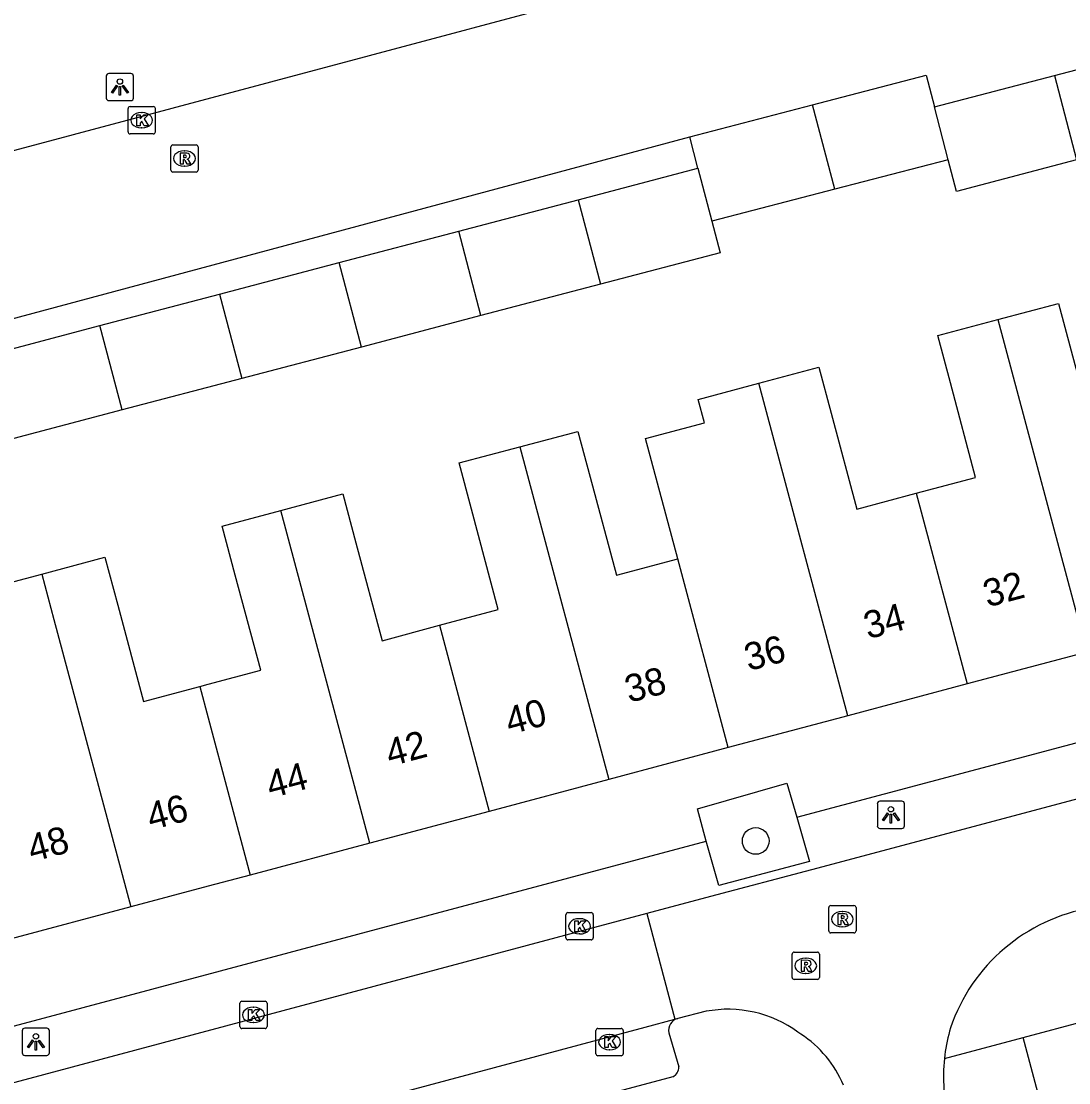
# Model space of a CAD drawing. Extents: x 162542 to 163144, y 380786 to 381511.
# Drawn here: x 162993.14 to 163031.56, y 381118.47 to 381157.4 of the extents above; entities that cross this region are included whole.
import ezdxf

# ---------------------------------------------------------------- set-up
doc = ezdxf.new("R2010")
doc.units = 0
for name, color, linetype in [('IMGEO_Boom', 7, 'Continuous'), ('IMGEO_Kolk', 7, 'Continuous'), ('IMGEO_Lichtpunt', 7, 'Continuous'), ('IMGEO_Pand', 7, 'Continuous'), ('IMGEO_Pand_nummerreeks', 7, 'Continuous'), ('IMGEO_Parkeervlak_open', 7, 'Continuous'), ('IMGEO_Rijbaan_lokaal_open', 7, 'Continuous'), ('IMGEO_Rioolput', 7, 'Continuous'), ('IMGEO_Voetpad_open', 7, 'Continuous')]:
    doc.layers.add(name, color=color, linetype=linetype)

msp = doc.modelspace()

# ---------------------------------------------------------------- linework, layer by layer
at = {"layer": 'IMGEO_Boom'}
msp.add_circle((163020.078, 381127.337), 0.489, dxfattribs=at)
at = {"layer": 'IMGEO_Kolk'}
for p, q in [((162997.059, 381153.341), (162997.059, 381154.193)), ((162997.134, 381154.267), (162997.986, 381154.267)), ((162998.06, 381154.193), (162998.06, 381153.341)), ((162997.547, 381154.047), (162997.572, 381154.047)), ((162997.57, 381153.487), (162997.545, 381153.487)), ((162997.986, 381153.267), (162997.134, 381153.267)), ((163013.118, 381123.782), (163013.118, 381124.634)), ((163013.193, 381124.708), (163014.045, 381124.708)), ((163014.119, 381124.634), (163014.119, 381123.782)), ((163013.606, 381124.488), (163013.631, 381124.488)), ((163013.629, 381123.928), (163013.604, 381123.928)), ((163014.045, 381123.708), (163013.193, 381123.708)), ((163001.159, 381120.532), (163001.159, 381121.384)), ((163001.234, 381121.458), (163002.086, 381121.458)), ((163002.16, 381121.384), (163002.16, 381120.532)), ((163001.647, 381121.238), (163001.672, 381121.238)), ((163001.67, 381120.678), (163001.645, 381120.678)), ((163002.086, 381120.458), (163001.234, 381120.458)), ((163014.218, 381119.536), (163014.218, 381120.388)), ((163014.293, 381120.462), (163015.145, 381120.462)), ((163014.706, 381120.242), (163014.731, 381120.242)), ((163015.219, 381120.388), (163015.219, 381119.536)), ((163015.145, 381119.462), (163014.293, 381119.462)), ((163014.729, 381119.682), (163014.704, 381119.682))]:
    msp.add_line(p, q, dxfattribs=at)
for points in [[(162997.059, 381153.341), (162997.059, 381154.193)], [(162997.134, 381154.267), (162997.986, 381154.267)], [(162998.06, 381154.193), (162998.06, 381153.341)], [(162997.38, 381153.967), (162997.503, 381153.967), (162997.503, 381153.816), (162997.633, 381153.967), (162997.797, 381153.967), (162997.651, 381153.816), (162997.804, 381153.567), (162997.652, 381153.567), (162997.567, 381153.731), (162997.503, 381153.664), (162997.503, 381153.567), (162997.38, 381153.567), (162997.38, 381153.967)], [(162997.986, 381153.267), (162997.134, 381153.267)], [(163013.118, 381123.782), (163013.118, 381124.634)], [(163013.193, 381124.708), (163014.045, 381124.708)], [(163014.119, 381124.634), (163014.119, 381123.782)], [(163013.439, 381124.408), (163013.562, 381124.408), (163013.562, 381124.257), (163013.692, 381124.408), (163013.856, 381124.408), (163013.71, 381124.257), (163013.863, 381124.008), (163013.711, 381124.008), (163013.626, 381124.172), (163013.562, 381124.105), (163013.562, 381124.008), (163013.439, 381124.008), (163013.439, 381124.408)], [(163014.045, 381123.708), (163013.193, 381123.708)], [(163001.159, 381120.532), (163001.159, 381121.384)], [(163001.234, 381121.458), (163002.086, 381121.458)], [(163002.16, 381121.384), (163002.16, 381120.532)], [(163001.48, 381121.158), (163001.603, 381121.158), (163001.603, 381121.007), (163001.733, 381121.158), (163001.897, 381121.158), (163001.751, 381121.007), (163001.904, 381120.758), (163001.752, 381120.758), (163001.667, 381120.922), (163001.603, 381120.855), (163001.603, 381120.758), (163001.48, 381120.758), (163001.48, 381121.158)], [(163002.086, 381120.458), (163001.234, 381120.458)], [(163014.218, 381119.536), (163014.218, 381120.388)], [(163014.293, 381120.462), (163015.145, 381120.462)], [(163015.219, 381120.388), (163015.219, 381119.536)], [(163014.539, 381120.162), (163014.662, 381120.162), (163014.662, 381120.011), (163014.792, 381120.162), (163014.956, 381120.162), (163014.81, 381120.011), (163014.963, 381119.762), (163014.811, 381119.762), (163014.726, 381119.926), (163014.662, 381119.859), (163014.662, 381119.762), (163014.539, 381119.762), (163014.539, 381120.162)], [(163015.145, 381119.462), (163014.293, 381119.462)]]:
    msp.add_lwpolyline(points, dxfattribs=at)
for centre, start, end in [((162997.136, 381154.191), 91.552, 178.448), ((162997.136, 381154.191), 91.552, 178.448), ((162997.984, 381154.191), 1.552, 88.448), ((162997.984, 381154.191), 1.552, 88.448), ((162997.136, 381153.343), 181.552, 268.448), ((162997.136, 381153.343), 181.552, 268.448), ((162997.984, 381153.343), 271.552, 358.448), ((162997.984, 381153.343), 271.552, 358.448), ((163013.195, 381124.632), 91.552, 178.448), ((163013.195, 381124.632), 91.552, 178.448), ((163014.043, 381124.632), 1.552, 88.448), ((163014.043, 381124.632), 1.552, 88.448), ((163013.195, 381123.784), 181.552, 268.448), ((163013.195, 381123.784), 181.552, 268.448), ((163014.043, 381123.784), 271.552, 358.448), ((163014.043, 381123.784), 271.552, 358.448), ((163001.236, 381121.382), 91.552, 178.448), ((163001.236, 381121.382), 91.552, 178.448), ((163002.084, 381121.382), 1.552, 88.448), ((163002.084, 381121.382), 1.552, 88.448), ((163001.236, 381120.534), 181.552, 268.448), ((163001.236, 381120.534), 181.552, 268.448), ((163002.084, 381120.534), 271.552, 358.448), ((163002.084, 381120.534), 271.552, 358.448), ((163014.295, 381120.386), 91.552, 178.448), ((163014.295, 381120.386), 91.552, 178.448), ((163015.143, 381120.386), 1.552, 88.448), ((163015.143, 381120.386), 1.552, 88.448), ((163014.295, 381119.538), 181.552, 268.448), ((163014.295, 381119.538), 181.552, 268.448), ((163015.143, 381119.538), 271.552, 358.448), ((163015.143, 381119.538), 271.552, 358.448)]:
    msp.add_arc(centre, 0.0765, start, end, dxfattribs=at)
for centre, major_axis, ratio, start_param, end_param in [((162997.546, 381153.767), (-0.387, 0.002), 0.722429, 4.712389, 7.853982), ((162997.571, 381153.767), (-0.39, 0.002), 0.717154, 1.570796, 4.712389), ((163013.605, 381124.208), (-0.387, 0.002), 0.722429, 4.712389, 7.853982), ((163013.63, 381124.208), (-0.39, 0.002), 0.717154, 1.570796, 4.712389), ((163001.646, 381120.958), (-0.387, 0.002), 0.722429, 4.712389, 7.853982), ((163001.671, 381120.958), (-0.39, 0.002), 0.717154, 1.570796, 4.712389), ((163014.705, 381119.962), (-0.387, 0.002), 0.722429, 4.712389, 7.853982), ((163014.73, 381119.962), (-0.39, 0.002), 0.717154, 1.570796, 4.712389)]:
    msp.add_ellipse(centre, major_axis=major_axis, ratio=ratio, start_param=start_param, end_param=end_param, dxfattribs=at)
at = {"layer": 'IMGEO_Lichtpunt'}
for p, q in [((162996.262, 381155.388), (162996.262, 381154.581)), ((162996.262, 381155.388), (162996.262, 381154.581)), ((162997.164, 381155.483), (162996.356, 381155.483)), ((162997.164, 381155.483), (162996.356, 381155.483)), ((162997.258, 381154.581), (162997.258, 381155.388)), ((162997.258, 381154.581), (162997.258, 381155.388)), ((162996.356, 381154.487), (162997.164, 381154.487)), ((162996.356, 381154.487), (162997.164, 381154.487)), ((163025.441, 381128.796), (163024.633, 381128.796)), ((163025.441, 381128.796), (163024.633, 381128.796)), ((163024.539, 381128.701), (163024.539, 381127.894)), ((163024.539, 381128.701), (163024.539, 381127.894)), ((163025.535, 381127.894), (163025.535, 381128.701)), ((163025.535, 381127.894), (163025.535, 381128.701)), ((163024.633, 381127.8), (163025.441, 381127.8)), ((163024.633, 381127.8), (163025.441, 381127.8)), ((162993.179, 381120.375), (162993.179, 381119.568)), ((162993.179, 381120.375), (162993.179, 381119.568)), ((162994.081, 381120.47), (162993.273, 381120.47)), ((162994.081, 381120.47), (162993.273, 381120.47)), ((162994.175, 381119.568), (162994.175, 381120.375)), ((162994.175, 381119.568), (162994.175, 381120.375)), ((162993.273, 381119.474), (162994.081, 381119.474)), ((162993.273, 381119.474), (162994.081, 381119.474))]:
    msp.add_line(p, q, dxfattribs=at)
for points in [[(162996.636, 381155.052), (162996.675, 381155.024), (162996.487, 381154.762), (162996.449, 381154.789), (162996.636, 381155.052)], [(162996.738, 381155.004), (162996.785, 381155.004), (162996.785, 381154.682), (162996.738, 381154.682), (162996.738, 381155.004)], [(162996.848, 381155.024), (162996.886, 381155.051), (162997.073, 381154.789), (162997.034, 381154.761), (162996.848, 381155.024)], [(163024.913, 381128.365), (163024.952, 381128.337), (163024.764, 381128.075), (163024.726, 381128.102), (163024.913, 381128.365)], [(163025.015, 381128.317), (163025.062, 381128.317), (163025.062, 381127.995), (163025.015, 381127.995), (163025.015, 381128.317)], [(163025.125, 381128.337), (163025.163, 381128.364), (163025.35, 381128.102), (163025.311, 381128.074), (163025.125, 381128.337)], [(162993.553, 381120.039), (162993.592, 381120.011), (162993.404, 381119.749), (162993.366, 381119.776), (162993.553, 381120.039)], [(162993.655, 381119.991), (162993.702, 381119.991), (162993.702, 381119.669), (162993.655, 381119.669), (162993.655, 381119.991)], [(162993.765, 381120.011), (162993.803, 381120.038), (162993.99, 381119.776), (162993.951, 381119.748), (162993.765, 381120.011)]]:
    msp.add_lwpolyline(points, dxfattribs=at)
for centre in [(162996.761, 381155.186), (163025.038, 381128.499), (162993.678, 381120.173)]:
    msp.add_circle(centre, 0.0994, dxfattribs=at)
for centre, start, end in [((162996.356, 381155.388), 90, 180), ((162996.356, 381155.388), 90, 180), ((162997.164, 381155.388), 0, 90), ((162997.164, 381155.388), 0, 90), ((162996.356, 381154.581), 180, 270), ((162996.356, 381154.581), 180, 270), ((162997.164, 381154.581), 270, 0), ((162997.164, 381154.581), 270, 360), ((163024.633, 381128.701), 90, 180), ((163024.633, 381128.701), 90, 180), ((163025.441, 381128.701), 0, 90), ((163025.441, 381128.701), 0, 90), ((163024.633, 381127.894), 180, 270), ((163024.633, 381127.894), 180, 270), ((163025.441, 381127.894), 270, 0), ((163025.441, 381127.894), 270, 360), ((162993.273, 381120.375), 90, 180), ((162993.273, 381120.375), 90, 180), ((162994.081, 381120.375), 0, 90), ((162994.081, 381120.375), 0, 90), ((162993.273, 381119.568), 180, 270), ((162993.273, 381119.568), 180, 270), ((162994.081, 381119.568), 270, 0), ((162994.081, 381119.568), 270, 360)]:
    msp.add_arc(centre, 0.0946, start, end, dxfattribs=at)
at = {"layer": 'IMGEO_Pand'}
for points in [[(163031.035, 381155.407), (163035.437, 381156.559)], [(163022.155, 381154.33), (163026.331, 381155.417), (163026.633, 381154.256)], [(163026.633, 381154.256), (163031.035, 381155.407)], [(163031.035, 381155.407), (163031.845, 381152.311)], [(163017.659, 381153.159), (163022.155, 381154.33)], [(163022.982, 381151.238), (163022.155, 381154.33)], [(163027.142, 381152.321), (163026.633, 381154.256)], [(163017.959, 381152.006), (163017.659, 381153.159)], [(163027.142, 381152.321), (163022.982, 381151.238)], [(163031.845, 381152.311), (163027.444, 381151.16), (163027.142, 381152.321)], [(163013.573, 381150.852), (163017.959, 381152.006)], [(163017.959, 381152.006), (163018.47, 381150.064)], [(163022.982, 381151.238), (163018.47, 381150.064)], [(163009.188, 381149.699), (163013.573, 381150.852)], [(163013.573, 381150.852), (163014.387, 381147.758)], [(163018.47, 381150.064), (163018.77, 381148.91), (163014.387, 381147.758)], [(163004.802, 381148.545), (163009.188, 381149.699)], [(163010.002, 381146.604), (163009.188, 381149.699)], [(163000.416, 381147.392), (163004.802, 381148.545)], [(163005.616, 381145.45), (163004.802, 381148.545)], [(163014.387, 381147.758), (163010.002, 381146.604)], [(162996.03, 381146.238), (163000.416, 381147.392)], [(163000.416, 381147.392), (163001.23, 381144.297)], [(163028.956, 381146.456), (163031.181, 381147.048), (163031.644, 381145.316), (163032.572, 381141.847), (163034.729, 381142.423), (163035.008, 381141.379)], [(163010.002, 381146.604), (163005.616, 381145.45)], [(163025.965, 381140.087), (163028.145, 381140.67), (163027.219, 381144.132), (163026.754, 381145.87), (163028.956, 381146.456)], [(163028.956, 381146.456), (163032.218, 381134.261)], [(162991.644, 381145.084), (162996.03, 381146.238)], [(162996.844, 381143.143), (162996.03, 381146.238)], [(163005.616, 381145.45), (163001.23, 381144.297)], [(163020.191, 381144.124), (163022.392, 381144.709), (163022.842, 381143.027), (163023.784, 381139.504), (163025.965, 381140.087)], [(163001.23, 381144.297), (162996.844, 381143.143)], [(163017.219, 381137.683), (163016.039, 381142.093), (163018.197, 381142.67), (163017.966, 381143.532), (163020.191, 381144.124)], [(163023.454, 381131.926), (163020.191, 381144.124)], [(162996.844, 381143.143), (162992.458, 381141.99)], [(163011.425, 381141.791), (163013.557, 381142.358), (163014.008, 381140.673), (163014.969, 381137.081), (163017.219, 381137.683)], [(163008.481, 381135.245), (163010.639, 381135.822), (163009.653, 381139.509), (163009.201, 381141.199), (163011.425, 381141.791)], [(163011.425, 381141.791), (163014.689, 381129.591)], [(163025.965, 381140.087), (163027.836, 381133.094)], [(163002.66, 381139.458), (163004.935, 381140.063), (163005.416, 381138.265), (163006.375, 381134.681), (163008.481, 381135.245)], [(162999.692, 381133.001), (163000, 381133.083), (163001.924, 381133.597), (163000.992, 381137.082), (163000.51, 381138.886), (163002.66, 381139.458)], [(163005.924, 381127.255), (163002.66, 381139.458)], [(162993.895, 381137.125), (162996.214, 381137.742), (162996.683, 381135.989), (162997.629, 381132.449), (162999.692, 381133.001)], [(163019.072, 381130.759), (163017.219, 381137.683)], [(162991.927, 381135.594), (162991.675, 381136.534), (162993.895, 381137.125)], [(162993.895, 381137.125), (162994.342, 381135.454), (162997.16, 381124.92)], [(163008.481, 381135.245), (163010.306, 381128.423)], [(163032.218, 381134.261), (163027.836, 381133.094)], [(163027.836, 381133.094), (163023.454, 381131.926)], [(162999.692, 381133.001), (163000, 381131.85), (163001.542, 381126.088)], [(163023.454, 381131.926), (163019.072, 381130.759)], [(163019.072, 381130.759), (163014.689, 381129.591)], [(163014.689, 381129.591), (163010.306, 381128.423)], [(163010.306, 381128.423), (163005.924, 381127.255)], [(163005.924, 381127.255), (163001.542, 381126.088)], [(163001.542, 381126.088), (163000, 381125.677), (162997.16, 381124.92)], [(162997.16, 381124.92), (162992.778, 381123.753)], [(163029.891, 381120.133), (163034.458, 381121.35)], [(163033.149, 381107.868), (163032.705, 381109.54), (163029.891, 381120.133)]]:
    msp.add_lwpolyline(points, dxfattribs=at)
at = {"layer": 'IMGEO_Parkeervlak_open'}
msp.add_lwpolyline([(163021.581, 381128.205), (163022.045, 381126.58), (163018.732, 381125.705), (163018.261, 381127.332)], dxfattribs=at)
at = {"layer": 'IMGEO_Rijbaan_lokaal_open'}
for points in [[(162947.453, 381140.539), (163071.786, 381173.732)], [(162946.538, 381134.062), (163017.659, 381153.159)], [(163032.672, 381129.087), (163022.13, 381126.273), (163018.423, 381125.304), (163016.087, 381124.68)], [(163016.087, 381124.68), (162980.601, 381115.195), (162980.082, 381115.076), (162975.55, 381113.864)], [(163016.087, 381124.68), (163017.107, 381120.8)], [(163018.257, 381121.091), (163017.219, 381120.83)], [(162980.068, 381110.891), (163016.022, 381120.51), (163017.107, 381120.8)], [(163017.107, 381120.8), (163017.219, 381120.83)], [(163021.739, 381120.256), (163021.628, 381120.331)], [(163027.221, 381120.484), (163027.191, 381120.367)]]:
    msp.add_lwpolyline(points, dxfattribs=at)
for centre, radius, start, end in [((163033.504, 381118.338), 6.639, 99.7095, 161.1412), ((163019.062, 381116.803), 4.362, 53.9622, 100.6277), ((163019.41, 381116.732), 4.224, 22.9321, 56.5349), ((163033.071, 381118.723), 6.105, 164.3777, 173.9909), ((163033.071, 381118.715), 6.106, 173.9148, 195.0124)]:
    msp.add_arc(centre, radius, start, end, dxfattribs=at)
at = {"layer": 'IMGEO_Rioolput'}
for p, q in [((162998.628, 381151.938), (162998.628, 381152.79)), ((162998.703, 381152.864), (162999.555, 381152.864)), ((162999.116, 381152.644), (162999.141, 381152.644)), ((162999.629, 381152.79), (162999.629, 381151.938)), ((162999.555, 381151.864), (162998.703, 381151.864)), ((162999.139, 381152.084), (162999.114, 381152.084)), ((163022.756, 381124.042), (163022.756, 381124.894)), ((163022.831, 381124.968), (163023.683, 381124.968)), ((163023.757, 381124.894), (163023.757, 381124.042)), ((163023.244, 381124.748), (163023.269, 381124.748)), ((163023.267, 381124.188), (163023.242, 381124.188)), ((163023.683, 381123.968), (163022.831, 381123.968)), ((163021.412, 381122.334), (163021.412, 381123.186)), ((163021.487, 381123.26), (163022.339, 381123.26)), ((163021.9, 381123.04), (163021.925, 381123.04)), ((163022.413, 381123.186), (163022.413, 381122.334)), ((163022.339, 381122.26), (163021.487, 381122.26)), ((163021.923, 381122.48), (163021.898, 381122.48))]:
    msp.add_line(p, q, dxfattribs=at)
for points in [[(162998.628, 381151.938), (162998.628, 381152.79)], [(162998.703, 381152.864), (162999.555, 381152.864)], [(162999.217, 381152.562), (162998.965, 381152.564), (162998.965, 381152.164)], [(162999.629, 381152.79), (162999.629, 381151.938)], [(162998.965, 381152.164), (162999.089, 381152.164), (162999.089, 381152.326), (162999.1, 381152.326)], [(162999.143, 381152.483), (162999.089, 381152.483), (162999.089, 381152.402)], [(162999.089, 381152.402), (162999.141, 381152.402)], [(162999.147, 381152.297), (162999.218, 381152.164), (162999.358, 381152.164), (162999.293, 381152.29)], [(162999.555, 381151.864), (162998.703, 381151.864)], [(163022.756, 381124.042), (163022.756, 381124.894)], [(163022.831, 381124.968), (163023.683, 381124.968)], [(163023.757, 381124.894), (163023.757, 381124.042)], [(163023.345, 381124.666), (163023.093, 381124.668), (163023.093, 381124.268)], [(163023.271, 381124.587), (163023.217, 381124.587), (163023.217, 381124.506)], [(163023.217, 381124.506), (163023.269, 381124.506)], [(163023.093, 381124.268), (163023.217, 381124.268), (163023.217, 381124.43), (163023.228, 381124.43)], [(163023.275, 381124.401), (163023.346, 381124.268), (163023.486, 381124.268), (163023.421, 381124.394)], [(163023.683, 381123.968), (163022.831, 381123.968)], [(163021.412, 381122.334), (163021.412, 381123.186)], [(163021.487, 381123.26), (163022.339, 381123.26)], [(163022.001, 381122.958), (163021.749, 381122.96), (163021.749, 381122.56)], [(163022.413, 381123.186), (163022.413, 381122.334)], [(163021.749, 381122.56), (163021.873, 381122.56), (163021.873, 381122.722), (163021.884, 381122.722)], [(163021.927, 381122.879), (163021.873, 381122.879), (163021.873, 381122.798)], [(163021.873, 381122.798), (163021.925, 381122.798)], [(163021.931, 381122.693), (163022.002, 381122.56), (163022.142, 381122.56), (163022.077, 381122.686)], [(163022.339, 381122.26), (163021.487, 381122.26)]]:
    msp.add_lwpolyline(points, dxfattribs=at)
for centre, radius, start, end in [((162998.705, 381152.788), 0.0765, 91.552, 178.448), ((162998.705, 381152.788), 0.0765, 91.552, 178.448), ((162999.216, 381152.452), 0.109, 350.3612, 89.416), ((162999.553, 381152.788), 0.0765, 1.552, 88.448), ((162999.553, 381152.788), 0.0765, 1.552, 88.448), ((162999.099, 381152.273), 0.0533, 26.0293, 88.6989), ((162999.125, 381152.591), 0.19, 274.7715, 282.9687), ((162999.149, 381152.387), 0.0964, 77.0061, 93.1865), ((162999.163, 381152.444), 0.0378, 276.6634, 79.6772), ((162999.214, 381152.452), 0.112, 277.5842, 350.9817), ((162999.198, 381152.237), 0.108, 29.5134, 73.7905), ((162998.705, 381151.94), 0.0765, 181.552, 268.448), ((162998.705, 381151.94), 0.0765, 181.552, 268.448), ((162999.553, 381151.94), 0.0765, 271.552, 358.448), ((162999.553, 381151.94), 0.0765, 271.552, 358.448), ((163022.833, 381124.892), 0.0765, 91.552, 178.448), ((163022.833, 381124.892), 0.0765, 91.552, 178.448), ((163023.681, 381124.892), 0.0765, 1.552, 88.448), ((163023.681, 381124.892), 0.0765, 1.552, 88.448), ((163023.253, 381124.695), 0.19, 274.7715, 282.9687), ((163023.277, 381124.491), 0.0964, 77.0061, 93.1865), ((163023.291, 381124.548), 0.0378, 276.6634, 79.6772), ((163023.344, 381124.556), 0.109, 350.3612, 89.416), ((163023.342, 381124.556), 0.112, 277.5842, 350.9817), ((163023.227, 381124.377), 0.0533, 26.0293, 88.6989), ((163023.326, 381124.341), 0.108, 29.5134, 73.7905), ((163022.833, 381124.044), 0.0765, 181.552, 268.448), ((163022.833, 381124.044), 0.0765, 181.552, 268.448), ((163023.681, 381124.044), 0.0765, 271.552, 358.448), ((163023.681, 381124.044), 0.0765, 271.552, 358.448), ((163021.489, 381123.184), 0.0765, 91.552, 178.448), ((163021.489, 381123.184), 0.0765, 91.552, 178.448), ((163022, 381122.848), 0.109, 350.3612, 89.416), ((163022.337, 381123.184), 0.0765, 1.552, 88.448), ((163022.337, 381123.184), 0.0765, 1.552, 88.448), ((163021.883, 381122.669), 0.0533, 26.0293, 88.6989), ((163021.909, 381122.987), 0.19, 274.7715, 282.9687), ((163021.933, 381122.783), 0.0964, 77.0061, 93.1865), ((163021.947, 381122.84), 0.0378, 276.6634, 79.6772), ((163021.998, 381122.848), 0.112, 277.5842, 350.9817), ((163021.982, 381122.633), 0.108, 29.5134, 73.7905), ((163021.489, 381122.336), 0.0765, 181.552, 268.448), ((163021.489, 381122.336), 0.0765, 181.552, 268.448), ((163022.337, 381122.336), 0.0765, 271.552, 358.448), ((163022.337, 381122.336), 0.0765, 271.552, 358.448)]:
    msp.add_arc(centre, radius, start, end, dxfattribs=at)
for centre, major_axis, ratio, start_param, end_param in [((162999.115, 381152.364), (-0.387, 0.002), 0.722429, 4.712389, 7.853982), ((162999.14, 381152.364), (-0.39, 0.002), 0.717154, 1.570796, 4.712389), ((163023.243, 381124.468), (-0.387, 0.002), 0.722429, 4.712389, 7.853982), ((163023.268, 381124.468), (-0.39, 0.002), 0.717154, 1.570796, 4.712389), ((163021.899, 381122.76), (-0.387, 0.002), 0.722429, 4.712389, 7.853982), ((163021.924, 381122.76), (-0.39, 0.002), 0.717154, 1.570796, 4.712389)]:
    msp.add_ellipse(centre, major_axis=major_axis, ratio=ratio, start_param=start_param, end_param=end_param, dxfattribs=at)
at = {"layer": 'IMGEO_Voetpad_open'}
for points in [[(163021.581, 381128.205), (163044.455, 381134.299)], [(163018.261, 381127.332), (163017.941, 381128.521), (163021.215, 381129.455), (163021.581, 381128.205)], [(162949.315, 381108.93), (162979.47, 381116.994), (162980.113, 381117.145), (163018.261, 381127.332)], [(163016.894, 381120.301), (163017.257, 381119.051)], [(163026.999, 381119.362), (163029.891, 381120.133)], [(163017.038, 381118.691), (162981.246, 381109.144)]]:
    msp.add_lwpolyline(points, dxfattribs=at)
for centre, radius, start, end in [((163017.337, 381120.393), 0.452, 105.1, 191.7697), ((163016.874, 381119.037), 0.383, 295.3433, 2.0296)]:
    msp.add_arc(centre, radius, start, end, dxfattribs=at)

# ---------------------------------------------------------------- texts
at = {"layer": 'IMGEO_Pand_nummerreeks'}
for s, rotation, p in [('32', 14.9191, (163028.576, 381135.9)), ('34', 14.9191, (163024.197, 381134.732)), ('36', 14.9191, (163019.815, 381133.564)), ('38', 14.9191, (163015.435, 381132.398)), ('40', 14.9191, (163011.053, 381131.23)), ('42', 14.9191, (163006.665, 381130.062)), ('44', 14.9191, (163002.286, 381128.894)), ('46', 14.9212, (162997.903, 381127.726)), ('48', 14.9198, (162993.535, 381126.561))]:
    msp.add_text(s, height=1, rotation=rotation, dxfattribs=at).set_placement(p)

doc.saveas('drawing.dxf')
